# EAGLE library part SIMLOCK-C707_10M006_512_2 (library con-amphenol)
C707A SIMLOCK® 2.5 mm with wide solder tails Source: Data sheet
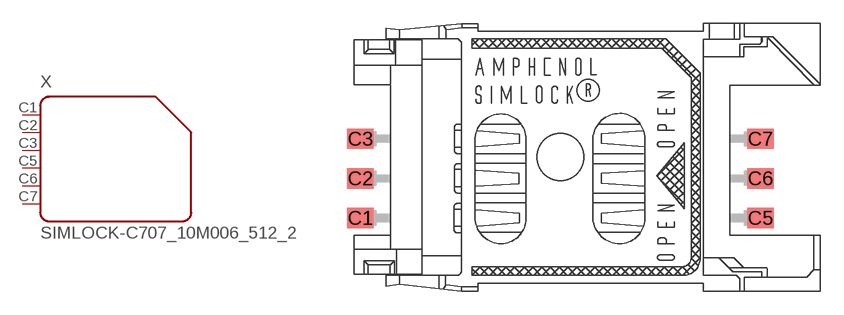
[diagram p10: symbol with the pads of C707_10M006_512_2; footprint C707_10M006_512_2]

Designator prefix X

## SIMLOCK-C707_10M006_512_2 (OC_FARNELL: unknown; OC_NEWARK: unknown)  [C707_10M006_512_2]
C1  1  pas
C2  2  pas
C3  3  pas
C5  4  pas
C6  5  pas
C7  6  pas

## Footprint C707_10M006_512_2 (pad centres in mm)
C707A SIMLOCK® 2.5 mm with wide solder tails Source: Data sheet
smd 1.7 x 1.3: C1 -12.85,-3.915; C2 -12.85,-1.375; C3 -12.85,1.165; C5 12.85,-3.915; C6 12.85,-1.375; C7 12.85,1.165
